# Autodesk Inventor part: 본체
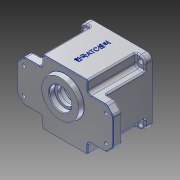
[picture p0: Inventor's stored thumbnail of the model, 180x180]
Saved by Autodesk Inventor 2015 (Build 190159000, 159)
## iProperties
Created: 2016-02
Part Number: 본체
Material: Aluminum 6061
Document SubType Name: Modeling
Designer: Administrator
Density: 2.7 g/cm^3
Appearance: Aluminum - Flat
Mass: 874.063 g
Surface Area: 762.876 cm^2
Volume: 323.727 cm^3
Author: Administrator
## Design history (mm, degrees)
sketch "Sketch1"
  geometry: L1 (-70, -30)-(70, -30); L2 (70, -30)-(70, 30); L3 (70, 30)-(-70, 30); L4 (-70, 30)-(-70, -30); L5 (-70, -30)-(70, 30); L6 (70, -30)-(-70, 30); 1 further point
  constraints: 12 end point, 2 midpoint, 2 parallel, 1 horizontal, 1 perpendicular
  dimensions: "d0" = 140 distance of L3.end L2.end; "d1" = 60 distance of L2.end L1.end
extrude "Extrusion1" new body sketch "Sketch1" distance "d2" = 13; taper "d3" = 0 deg
sketch "Sketch2"
  geometry: L1 (-33, -47)-(33, -47); L2 (33, -47)-(33, 47); L3 (33, 47)-(-33, 47); L4 (-33, 47)-(-33, -47); L5 (-33, -47)-(33, 47); L6 (33, -47)-(-33, 47); 1 further point
  constraints: 12 end point, 2 midpoint, 2 parallel, 1 horizontal, 1 perpendicular
  dimensions: "d4" = 66 distance of L3.end L2.end; "d5" = 94 distance of L2.end L1.end
extrude "Extrusion2" join sketch "Sketch2" distance "d6" = 80; taper "d7" = 0 deg
sketch "Sketch3"
  geometry: L1 (-47, 47)-(47, 47); L2 (47, 47)-(47, -47); L3 (47, -47)-(-47, -47); L4 (-47, -47)-(-47, 47); L5 (-47, 47)-(47, -47); L6 (47, 47)-(-47, -47); 1 further point
  constraints: 12 end point, 2 midpoint, 2 parallel, 1 horizontal, 1 perpendicular
  dimensions: "d8" = 94 distance of L2.end L3.end; "d9" = 94 distance of L1.end L2.end
extrude "Extrusion3" join sketch "Sketch3" distance "d10" = 10; taper "d11" = 0 deg
sketch "Sketch4"
  geometry: L1 (-47, 30)-(47, 30); L2 (47, 30)-(47, -30); L3 (47, -30)-(-47, -30); L4 (-47, -30)-(-47, 30); L5 (-47, 30)-(47, -30); L6 (47, 30)-(-47, -30); 1 further point
  constraints: 12 end point, 2 midpoint, 2 parallel, 1 horizontal, 1 perpendicular
  dimensions: "d12" = 60 distance of L1.end L2.end; "d13" = 94 distance of L2.end L3.end
extrude "Extrusion4" join sketch "Sketch4" stored distance "d14" = 10; taper "d15" = 0 deg
sketch "Sketch5"
  geometry: C1 r 43 at (0, 0); 1 further point
  constraints: 1 centre point, 1 coincident
  dimensions: "d16" = 86 diameter of C1
extrude "Extrusion5" cut sketch "Sketch5" distance "d17" = 9; taper "d18" = 0 deg
sketch "Sketch6"
  geometry: C1 r 43 at (0, 0) reference; C2 r 40 at (0, 0); 1 further point
  constraints: 1 centre point, 1 coincident
  dimensions: "d19" = 80 diameter of C2
extrude "Extrusion6" cut sketch "Sketch6" distance "d20" = 62; taper "d21" = 0 deg
sketch "Sketch7"
  geometry: L1 (36, 0)-(-36, 0); L2 (39.799, -4)-(35.777, -4); L3 (39.799, 4)-(35.777, 4); L4 (-35.777, -4)-(-39.799, -4); L5 (-35.777, 4)-(-39.799, 4); A1 r 40 centre (0, 0) between (-39.799, -4) and (-39.799, 4) reference; A2 r 36 centre (0, 0) between (36, 0) and (-36, 0); A3 r 4 centre (36, 0) between (36, 4) and (36, -4); A4 r 4 centre (-36, 0) between (-36, -4) and (-36, 4); 4 further points
  constraints: 14 point on circle, 10 end point, 6 coincident, 5 horizontal, 4 point on line, 4 tangent, 3 centre point, 1 midpoint
  dimensions: "d22" = 72 diameter of A2; "d23" = 8 diameter of A3; "d24" = 8 diameter of A4
extrude "Extrusion7" join sketch "Sketch7" stored distance "d25" = 62; taper "d26" = 0 deg
fillet "Fillet1" dims "d27" = 3.5
hole "Hole1" sketch "Sketch7" diameter "d28" = 3.242; stored, may be unused: countersink angle "d32" = 90 deg, drill point angle "d34" = 118 deg; dims "d29" = 7, "d30" = 4, "d31" = 2, "d33" = 9
sketch "Sketch8"
  geometry: C1 r 28 at (0, 11); 1 further point
  constraints: 1 centre point, 1 vertical alignment
  dimensions: "d35" = 56 diameter of C1; "d36" = 11 distance of point (0, 0) C1.centre
extrude "Extrusion8" join sketch "Sketch8" distance "d37" = 7; taper "d38" = -10 deg
hole "Hole2" diameter "d41" = 25; stored, may be unused: countersink angle "d45" = 90 deg, drill point angle "d47" = 0 deg; dims "d39" = 10, "d40" = 10, "d42" = 7, "d43" = 32, "d44" = 8, "d46" = 13
sketch "Sketch9"
  geometry: A1 r 21 centre (0, -11) between (-8.978, 7.984) and (8.978, 7.984); A2 r 15 centre (0, 20) between (8.978, 7.984) and (-8.978, 7.984); 1 further point
  constraints: 4 point on circle, 2 centre point, 2 vertical alignment
  dimensions: "d48" = 42 diameter of A1; "d49" = 11 distance of A1.centre point (0, 0); "d50" = 30 diameter of A2; "d51" = 20 distance of A2.centre point (0, 0)
extrude "Extrusion9" join sketch "Sketch9" distance "d52" = 7; taper "d53" = 0 deg
fillet "Fillet2" dims "d54" = 3
hole "Hole3" diameter "d57" = 19; stored, may be unused: countersink angle "d61" = 90 deg, drill point angle "d63" = 0 deg; dims "d55" = 10, "d56" = 10, "d58" = 7, "d59" = 22, "d60" = 7, "d62" = 8
hole "Hole4" diameter "d66" = 25; stored, may be unused: countersink angle "d70" = 90 deg, drill point angle "d72" = 0 deg; dims "d64" = 10, "d65" = 10, "d67" = 7, "d68" = 35, "d69" = 10, "d71" = 15
chamfer "Chamfer1" distance "d73" = 1; stored, may be unused: second distance "d74" = 2, angle "d75" = 45 deg
sketch "Sketch10"
  geometry: L1 (47, 47)-(47, -47) reference; L2 (-47, 47)-(47, 47) reference; L3 (-47, -47)-(-47, 47) reference; L4 (47, -47)-(-47, -47) reference; L5 (-40, 40)-(40, 40); L6 (40, 40)-(40, -40); L7 (40, -40)-(-40, -40); L8 (-40, -40)-(-40, 40); L9 (-40, 40)-(40, -40); L10 (40, 40)-(-40, -40); C1 r 43 at (0, 0) reference; 5 further points
  constraints: 12 end point, 4 coincident, 2 midpoint, 2 parallel, 1 horizontal, 1 perpendicular
  dimensions: "d76" = 80 distance of L6.end L7.end; "d77" = 80 distance of L5.end L6.end
hole "Hole5" sketch "Sketch10" at (40, -40), (40, 40), (-40, 40), (-40, -40) diameter "d78" = 7; stored, may be unused: countersink angle "d82" = 90 deg, drill point angle "d84" = 0 deg; dims "d79" = 7, "d80" = 35, "d81" = 10, "d83" = 15
workplane "Work Plane1"
sketch "Sketch13"
  geometry: L1 (70, 30)-(33, 30) reference; L2 (70, -30)-(70, 30) reference; L3 (33, -30)-(70, -30) reference; L4 (33, -30)-(33, -47) reference; L5 (33, -47)-(-33, -47) reference; L6 (-33, -47)-(-33, -30) reference; L7 (-70, -30)-(-33, -30) reference; L8 (-70, 30)-(-70, -30) reference; L9 (-33, 30)-(-70, 30) reference; L10 (-33, 30)-(-33, 47) reference; L11 (-33, 47)-(33, 47) reference; L12 (33, 47)-(33, 30) reference; L13 (-60, -19)-(60, -19); L14 (60, -19)-(60, 19); L15 (60, 19)-(-60, 19); L16 (-60, 19)-(-60, -19); L17 (-60, -19)-(60, 19); L18 (60, -19)-(-60, 19); C1 r 28 at (0, 11) reference; 5 further points
  constraints: 12 end point, 4 coincident, 2 midpoint, 2 parallel, 1 horizontal, 1 perpendicular
  dimensions: "d88" = 120 distance of L15.end L14.end; "d89" = 38 distance of L14.end L13.end
hole "Hole6" sketch "Sketch13" at (60, -19), (60, 19), (-60, -19), (-60, 19) diameter "d90" = 5; stored, may be unused: countersink angle "d94" = 90 deg, drill point angle "d96" = 0 deg; dims "d91" = 7, "d92" = 9, "d93" = 4, "d95" = 15
fillet "Fillet3" dims "d97" = 0.3
chamfer "Chamfer2" distance "d98" = 10; stored, may be unused: second distance "d99" = 2, angle "d100" = 45 deg
fillet "Fillet4" dims "d101" = 8
sketch "Sketch14"
  geometry: L1 (70, -20)-(60, -30) reference; L2 (70, 20)-(70, -20) reference; L3 (60, 30)-(70, 20) reference; L4 (33, 30)-(60, 30) reference; L5 (33, 30)-(33, 47) reference; L6 (33, 47)-(-33, 47) reference; L7 (-33, 47)-(-33, 30) reference; L8 (-60, 30)-(-33, 30) reference; L9 (-70, 20)-(-60, 30) reference; L10 (-70, -20)-(-70, 20) reference; L11 (-60, -30)-(-70, -20) reference; L12 (-33, -30)-(-60, -30) reference; L13 (-33, -30)-(-33, -47) reference; L14 (-33, -47)-(33, -47) reference; L15 (33, -47)-(33, -30) reference; L16 (60, -30)-(33, -30) reference; L17 (32, -29)-(32, -46); L18 (32, -46)-(-32, -46); L19 (-32, -46)-(-32, -29); L20 (-32, -29)-(-59.586, -29); L21 (-59.586, -29)-(-69, -19.586); L22 (-69, -19.586)-(-69, 19.586); L23 (-69, 19.586)-(-59.586, 29); L24 (-59.586, 29)-(-32, 29); L25 (-32, 29)-(-32, 46); L26 (-32, 46)-(32, 46); L27 (32, 46)-(32, 29); L28 (32, 29)-(59.586, 29); L29 (59.586, 29)-(69, 19.586); L30 (69, 19.586)-(69, -19.586); L31 (69, -19.586)-(59.586, -29); L32 (59.586, -29)-(32, -29); C1 r 2.5 at (60, -19) reference; C2 r 2.5 at (-60, -19) reference; C3 r 2.5 at (-60, 19) reference; C4 r 2.5 at (60, 19) reference; C5 r 28 at (0, 11) reference; 1 further point
  constraints: 32 end point, 15 other
  dimensions: "d102" = 1 distance between parallel lines of L16 L32
extrude "Extrusion10" cut sketch "Sketch14" distance "d103" = 1; taper "d104" = 0 deg
fillet "Fillet8" dims "d108" = 5
fillet "Fillet9" dims "d109" = 5
fillet "Fillet10" dims "d110" = 2
fillet "Fillet11" dims "d111" = 2
fillet "Fillet14" dims "d114" = 2
fillet "Fillet18" dims "d118" = 2
sketch "Sketch15"
  geometry: L1 (78, 0)-(0, 0) reference; 2 further points
  constraints: 1 vertical alignment, 1 other
  dimensions: "d119" = 40 distance from line of L1 point (39, -40)
emboss "Emboss1" sketch "Sketch15" dims "d8" = 94, "d9" = 94, "d120" = 0.5, "d121" = 0
fillet "Fillet20" dims "d123" = 0.3
fillet "Fillet21" dims "d124" = 2
fillet "Fillet22" dims "d125" = 5
fillet "Fillet23" dims "d126" = 5
fillet "Fillet24" dims "d127" = 2
fillet "Fillet25" dims "d128" = 2
fillet "Fillet26" dims "d129" = 2
fillet "Fillet27" dims "d130" = 2
body "Solid1"
node "Projected Loop1"
node "Projected Loop2"
node "Projected Loop4"
node "Projected Loop5"
other parameters: "d87" = 13
